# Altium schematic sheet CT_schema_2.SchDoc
size 276 x 169 mm
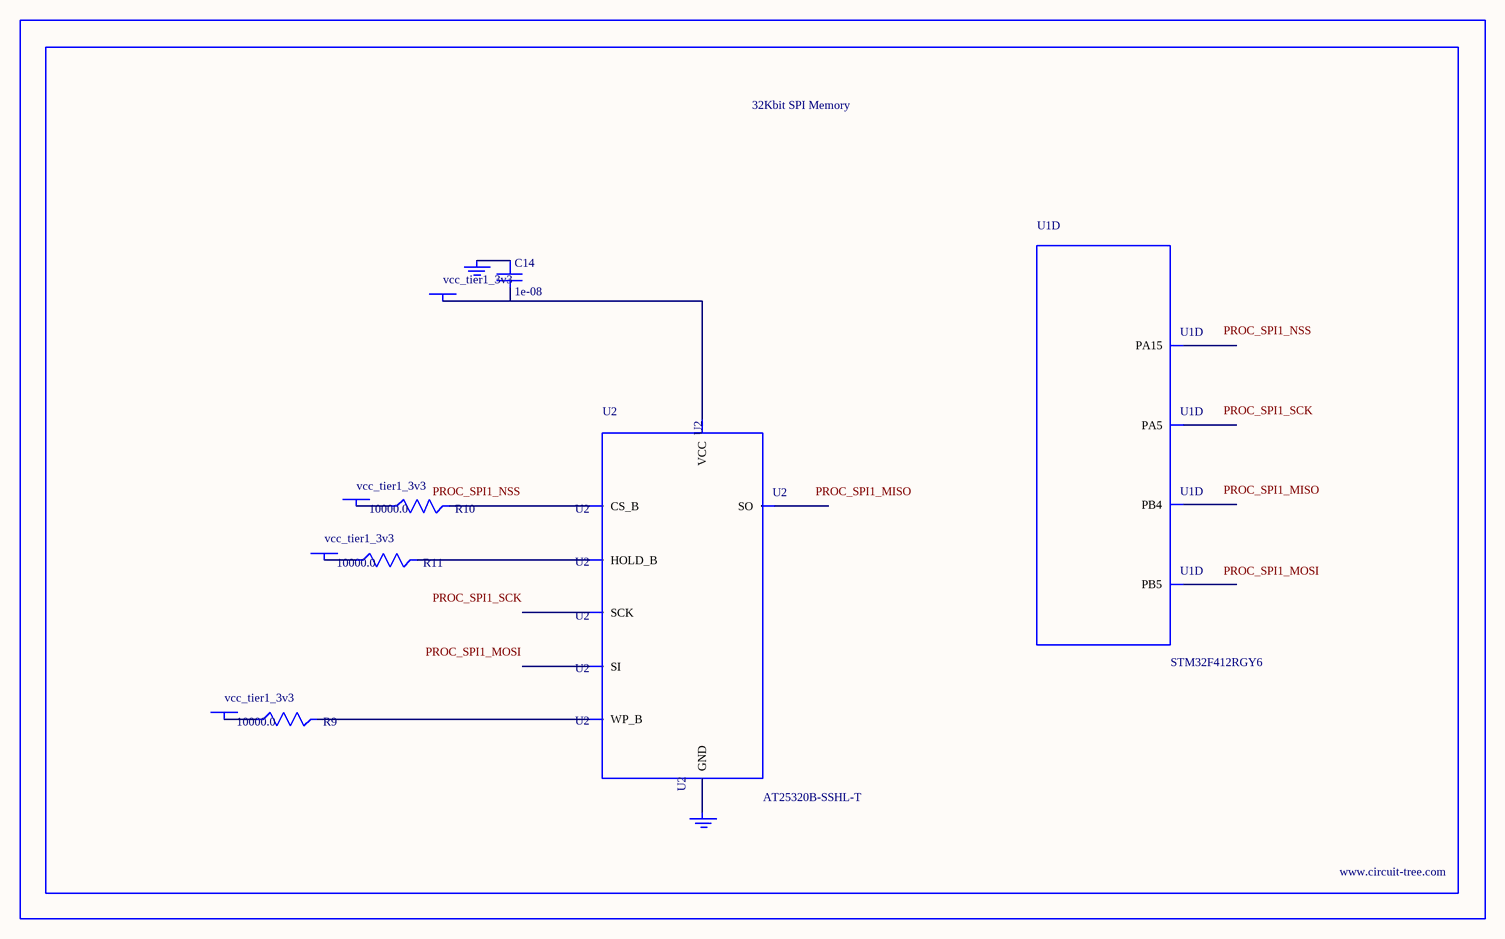
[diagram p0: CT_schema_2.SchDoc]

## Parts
BORDER1  (no value)
C14  1e-08  [C0402]
GND_INSTANCE_1_0  (no value)
GND_INSTANCE_1_1  (no value)
POWER_INSTANCE_1_0  vcc_tier1_3v3
POWER_INSTANCE_1_1  vcc_tier1_3v3
POWER_INSTANCE_1_2  vcc_tier1_3v3
POWER_INSTANCE_1_3  vcc_tier1_3v3
R9  10000.0  [R0603]
R10  10000.0  [R0603]
R11  10000.0  [R0603]
U1  STM32F412RGY6  [WLCSP64]  (part D of 7)
U2  AT25320B-SSHL-T  [SOIC-8]

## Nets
NetC14_1: C14.1 GND_INSTANCE_1_0.0(GND)
NetC14_2: C14.2 POWER_INSTANCE_1_3.0(PWR) U2.8(VCC)
NetGND_INSTANCE_1_1_0: GND_INSTANCE_1_1.0(GND) U2.4(GND)
NetPOWER_INSTANCE_1_0_0: POWER_INSTANCE_1_0.0(PWR) R10.1
NetPOWER_INSTANCE_1_1_0: POWER_INSTANCE_1_1.0(PWR) R9.1
NetPOWER_INSTANCE_1_2_0: POWER_INSTANCE_1_2.0(PWR) R11.1
NetR9_2: R9.2 U2.3(WP_B)
NetR10_2: R10.2 U2.1(CS_B)
NetR11_2: R11.2 U2.7(HOLD_B)

Not connected (* = marked no-connect by the designer): U1 A2(PA15) B4(PB4) C4(PB5) F5(PA5); U2 2(SO) 5(SI) 6(SCK)

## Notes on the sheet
- Labels drawn without touching a wire or pin: PROC_SPI1_MISO, PROC_SPI1_MOSI, PROC_SPI1_NSS, PROC_SPI1_SCK

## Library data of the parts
BORDER1 = BORDER_PAGE1
C14 = C0402C103K3RAC
GND_INSTANCE_1_0 GND_INSTANCE_1_1 = GND
POWER_INSTANCE_1_0-POWER_INSTANCE_1_3 = PWR
R9-R11 = RC0603JR-0710KL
